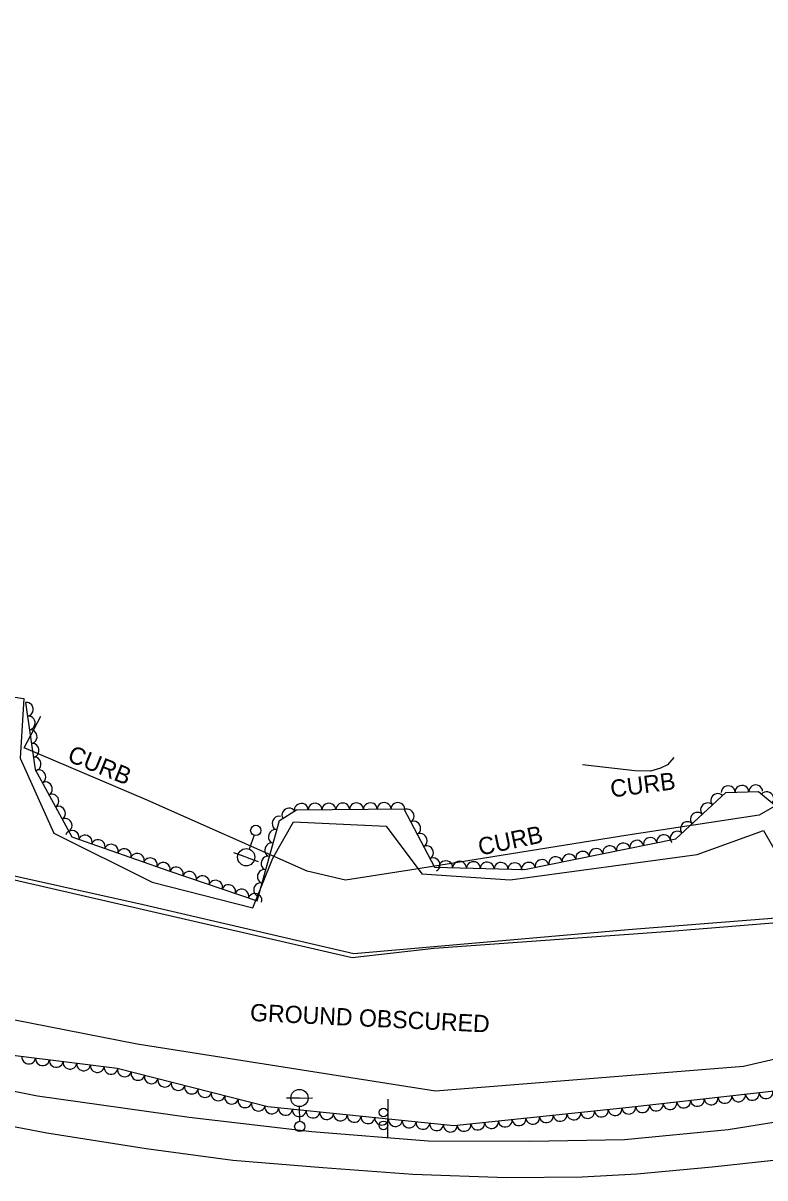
# Model space of a CAD drawing. Extents: x 1722896 to 1754269, y 648279 to 666297.
# Drawn here: x 1729327.9 to 1729542.8, y 652843.6 to 653178.1 of the extents above; entities that cross this region are included whole.
import ezdxf

# ---------------------------------------------------------------- set-up
doc = ezdxf.new("R2010")
doc.units = 0
for name, color, linetype in [('DESIGN - PUBLIC HEARING - Shapes', 7, 'Continuous'), ('DESIGN - SCRATCH - User 1', 7, 'Continuous'), ('SURVEY - CENTERLINE - Preliminary', 7, 'Continuous'), ('SURVEY - CENTERLINE - Preliminary Text', 7, 'Continuous'), ('SURVEY - DTM - Breaklines', 7, 'Continuous'), ('SURVEY - VEGETATION - Features with Text', 7, 'Continuous')]:
    doc.layers.add(name, color=color, linetype=linetype)

msp = doc.modelspace()

# ---------------------------------------------------------------- linework, layer by layer
at = {"layer": 'DESIGN - PUBLIC HEARING - Shapes'}
msp.add_line((1729433.54, 652866.38), (1729433.46, 652855.18), dxfattribs=at)
for centre in [(1729432.29, 652862.57), (1729432.26, 652858.82)]:
    msp.add_circle(centre, 1.25, dxfattribs=at)
at = {"layer": 'DESIGN - SCRATCH - User 1'}
for points in [[(1730402.95, 653127.46), (1730314.28, 653134.59), (1730219.17, 653162.83), (1730167.73, 653178.08), (1730100.62, 653177.14), (1730014.99, 653177.64), (1729990.41, 653163.02), (1729903.69, 653112.98), (1729836.86, 653073.47), (1729767.22, 653033.19), (1729728.41, 653010.36), (1729689.91, 652988.22), (1729640.73, 652959.93), (1729615.49, 652945.23), (1729574.28, 652921.03), (1729503.17, 652915.44), (1729423.74, 652908.46), (1729362.64, 652922.7), (1729266.32, 652944.1)], [(1729325.44, 652929.93), (1729423.21, 652907.47), (1729447.01, 652910.13), (1729515.48, 652915.11), (1729574.72, 652919.93), (1729618.03, 652944.86), (1729690.89, 652987.57), (1729742.07, 653016.84), (1729803.78, 653052.91), (1729873.89, 653094.15), (1729936.09, 653129.87), (1729994.48, 653163.92), (1730014.5, 653175.61), (1730021, 653175.83), (1730100.23, 653175.61), (1730167.67, 653176.58), (1730218.67, 653161.51), (1730268.57, 653146.66), (1730315.51, 653132.74), (1730411.72, 653125.99)]]:
    msp.add_lwpolyline(points, dxfattribs=at)
at = {"layer": 'SURVEY - CENTERLINE - Preliminary'}
for points in [[(1729307.77, 652985.42), (1729328.13, 652982.44), (1729327.01, 652965.19), (1729336.81, 652943.5), (1729365.32, 652929.31), (1729394.46, 652921.79), (1729400.28, 652936.17), (1729406.2, 652946.74), (1729433.08, 652945.51), (1729443.4, 652931.68), (1729469.04, 652929.95), (1729523.19, 652937.25), (1729542.35, 652944.25), (1729548.04, 652934.5)], [(1729579.47, 652885.83), (1729536.63, 652875.85), (1729447.41, 652868.7), (1729360.96, 652882.35), (1729268.83, 652900.44)]]:
    msp.add_lwpolyline(points, dxfattribs=at)
at = {"layer": 'SURVEY - CENTERLINE - Preliminary Text'}
for points in [[(1729963, 653167.59), (1729899.51, 653130.82), (1729894.39, 653138.3), (1729886.38, 653132.61), (1729890.7, 653126), (1729855.67, 653106.22), (1729807.21, 653078.99), (1729736.41, 653038.91), (1729700.34, 653018.37), (1729665.67, 652998.66), (1729621.6, 652973.6), (1729593.97, 652958.91), (1729586.08, 652970.67), (1729582.54, 652971.88), (1729578.25, 652969.91), (1729564.1, 652961.86), (1729541.14, 652948.7), (1729503.07, 652942.92), (1729440.49, 652932.87), (1729421.3, 652929.88), (1729410.15, 652932.46), (1729363.18, 652953.33), (1729328.22, 652968.2), (1729333.04, 652977.32)], [(1729516.4, 652965.39), (1729514.6, 652963.25), (1729512.59, 652962.27), (1729509.69, 652961.42), (1729505.15, 652961.52), (1729489.94, 652963.22)], [(1729332.06, 652867.31), (1729297.74, 652874.16), (1729251.92, 652884.16), (1729185.5, 652898.55), (1729112.25, 652914.71), (1729058.49, 652927.72), (1729008.62, 652939.2)], [(1729593.11, 652889.86), (1729590.97, 652879.49), (1729583.67, 652866.62), (1729562.77, 652862.48), (1729532.16, 652857.56), (1729502.1, 652854.67), (1729474.71, 652854.17), (1729445.23, 652854.27), (1729411.53, 652856.98), (1729375.99, 652861.08), (1729332.06, 652867.31)], [(1729545.25, 652848.67), (1729527.55, 652846.69), (1729505.69, 652844.72), (1729489.9, 652843.84), (1729467.9, 652843.61), (1729440.82, 652844.63), (1729414.69, 652846.51), (1729388.67, 652848.67), (1729363.54, 652851.99), (1729334.74, 652856.56), (1729293.83, 652864.36)]]:
    msp.add_lwpolyline(points, dxfattribs=at)
at = {"layer": 'SURVEY - DTM - Breaklines'}
for p, q in [((1729394.8, 652942.84), (1729393.36, 652938.84)), ((1729392.52, 652936.49), (1729388.99, 652937.75)), ((1729392.52, 652936.49), (1729396.04, 652935.22)), ((1729407.96, 652866.75), (1729404.21, 652866.71)), ((1729407.96, 652866.75), (1729411.71, 652866.8)), ((1729408.05, 652860), (1729407.99, 652864.25))]:
    msp.add_line(p, q, dxfattribs=at)
for centre, radius in [((1729395.3, 652944.25), 1.5), ((1729392.52, 652936.49), 2.5), ((1729407.96, 652866.75), 2.5), ((1729408.06, 652858.5), 1.5)]:
    msp.add_circle(centre, radius, dxfattribs=at)
at = {"layer": 'SURVEY - VEGETATION - Features with Text'}
for points in [[(1729975.99, 653117.37), (1729899.53, 653059.57), (1729865.08, 653028.08), (1729823.22, 653000), (1729781.82, 652967.28), (1729747.33, 652941.84), (1729709.92, 652918.75), (1729671.39, 652897.72), (1729627.16, 652881.54), (1729611.02, 652880.54), (1729603.59, 652887.52), (1729589.11, 652879.56), (1729560.05, 652870.34), (1729503.49, 652863.99), (1729452.68, 652858.67), (1729398.78, 652864.16), (1729355.14, 652875.31), (1729312.42, 652880.62)], [(1729328.62, 652981.34), (1729331.41, 652961.94), (1729341.98, 652942.35), (1729370.13, 652932.5), (1729395.7, 652923.86), (1729402.16, 652947.16), (1729407.14, 652950.17), (1729438.21, 652950.46), (1729447.12, 652933.64), (1729473.2, 652932.9), (1729517, 652941.81), (1729531.47, 652955.25), (1729540.99, 652955.56), (1729550.02, 652948.02)]]:
    msp.add_lwpolyline(points, dxfattribs=at)
for centre, major_axis in [((1729328.91, 652979.36), (0.28, -1.98)), ((1729329.48, 652975.4), (0.28, -1.98)), ((1729330.05, 652971.44), (0.28, -1.98)), ((1729330.62, 652967.48), (0.28, -1.98)), ((1729331.19, 652963.52), (0.28, -1.98)), ((1729332.55, 652959.83), (0.95, -1.76)), ((1729334.45, 652956.31), (0.95, -1.76)), ((1729532.15, 652955.27), (2, 0.06)), ((1729536.15, 652955.4), (2, 0.06)), ((1729540.15, 652955.53), (2, 0.06)), ((1729543.41, 652953.53), (1.54, -1.28)), ((1729336.35, 652952.79), (0.95, -1.76)), ((1729408.48, 652950.18), (2, 0.02)), ((1729412.48, 652950.22), (2, 0.02)), ((1729416.48, 652950.26), (2, 0.02)), ((1729420.48, 652950.3), (2, 0.02)), ((1729424.48, 652950.33), (2, 0.02)), ((1729428.48, 652950.37), (2, 0.02)), ((1729432.48, 652950.41), (2, 0.02)), ((1729436.47, 652950.45), (2, 0.02)), ((1729526.11, 652950.27), (1.47, 1.36)), ((1729529.04, 652952.99), (1.47, 1.36)), ((1729338.25, 652949.27), (0.95, -1.76)), ((1729404.86, 652948.79), (1.71, 1.03)), ((1729439.27, 652948.46), (0.94, -1.77)), ((1729523.18, 652947.55), (1.47, 1.36)), ((1729340.15, 652945.75), (0.95, -1.76)), ((1729401.94, 652946.34), (0.53, 1.93)), ((1729441.14, 652944.93), (0.94, -1.77)), ((1729520.25, 652944.83), (1.47, 1.36)), ((1729342.12, 652942.31), (1.89, -0.66)), ((1729345.89, 652940.99), (1.89, -0.66)), ((1729400.87, 652942.49), (0.53, 1.93)), ((1729443.01, 652941.39), (0.94, -1.77)), ((1729509.59, 652940.3), (1.96, 0.4)), ((1729513.5, 652941.1), (1.96, 0.4)), ((1729517.32, 652942.1), (1.47, 1.36)), ((1729349.67, 652939.66), (1.89, -0.66)), ((1729353.44, 652938.34), (1.89, -0.66)), ((1729357.22, 652937.02), (1.89, -0.66)), ((1729399.8, 652938.63), (0.53, 1.93)), ((1729444.88, 652937.86), (0.94, -1.77)), ((1729493.91, 652937.11), (1.96, 0.4)), ((1729497.83, 652937.91), (1.96, 0.4)), ((1729501.75, 652938.7), (1.96, 0.4)), ((1729505.67, 652939.5), (1.96, 0.4)), ((1729360.99, 652935.7), (1.89, -0.66)), ((1729364.77, 652934.38), (1.89, -0.66)), ((1729398.73, 652934.78), (0.53, 1.93)), ((1729446.75, 652934.32), (0.94, -1.77)), ((1729450.34, 652933.55), (2, -0.06)), ((1729454.34, 652933.43), (2, -0.06)), ((1729478.23, 652933.92), (1.96, 0.4)), ((1729482.15, 652934.72), (1.96, 0.4)), ((1729486.07, 652935.51), (1.96, 0.4)), ((1729489.99, 652936.31), (1.96, 0.4)), ((1729368.54, 652933.06), (1.89, -0.66)), ((1729372.33, 652931.76), (1.89, -0.64)), ((1729376.12, 652930.48), (1.89, -0.64)), ((1729397.66, 652930.93), (0.53, 1.93)), ((1729458.34, 652933.32), (2, -0.06)), ((1729462.34, 652933.2), (2, -0.06)), ((1729466.33, 652933.09), (2, -0.06)), ((1729470.33, 652932.98), (2, -0.06)), ((1729474.31, 652933.12), (1.96, 0.4)), ((1729379.91, 652929.2), (1.89, -0.64)), ((1729383.7, 652927.92), (1.89, -0.64)), ((1729387.49, 652926.64), (1.89, -0.64)), ((1729396.59, 652927.07), (0.53, 1.93)), ((1729391.28, 652925.36), (1.89, -0.64)), ((1729395.07, 652924.08), (1.89, -0.64)), ((1729329.54, 652878.49), (-1.98, 0.25)), ((1729333.51, 652878), (-1.98, 0.25)), ((1729337.48, 652877.51), (-1.98, 0.25)), ((1729341.45, 652877.01), (-1.98, 0.25)), ((1729345.42, 652876.52), (-1.98, 0.25)), ((1729349.39, 652876.03), (-1.98, 0.25)), ((1729353.36, 652875.53), (-1.98, 0.25)), ((1729357.27, 652874.77), (-1.94, 0.49)), ((1729361.15, 652873.78), (-1.94, 0.49)), ((1729365.02, 652872.79), (-1.94, 0.49)), ((1729368.9, 652871.8), (-1.94, 0.49)), ((1729372.78, 652870.81), (-1.94, 0.49)), ((1729376.65, 652869.82), (-1.94, 0.49)), ((1729380.53, 652868.83), (-1.94, 0.49)), ((1729543.13, 652868.44), (-1.99, -0.22)), ((1729384.4, 652867.84), (-1.94, 0.49)), ((1729388.28, 652866.85), (-1.94, 0.49)), ((1729392.15, 652865.86), (-1.94, 0.49)), ((1729396.03, 652864.87), (-1.94, 0.49)), ((1729515.31, 652865.31), (-1.99, -0.22)), ((1729519.28, 652865.76), (-1.99, -0.22)), ((1729523.26, 652866.21), (-1.99, -0.22)), ((1729527.23, 652866.65), (-1.99, -0.22)), ((1729531.21, 652867.1), (-1.99, -0.22)), ((1729535.18, 652867.55), (-1.99, -0.22)), ((1729539.16, 652867.99), (-1.99, -0.22)), ((1729399.93, 652864.05), (-1.99, 0.2)), ((1729403.91, 652863.64), (-1.99, 0.2)), ((1729407.89, 652863.24), (-1.99, 0.2)), ((1729411.87, 652862.83), (-1.99, 0.2)), ((1729415.85, 652862.42), (-1.99, 0.2)), ((1729419.83, 652862.02), (-1.99, 0.2)), ((1729423.81, 652861.61), (-1.99, 0.2)), ((1729483.49, 652861.89), (-1.99, -0.21)), ((1729487.47, 652862.31), (-1.99, -0.21)), ((1729491.45, 652862.73), (-1.99, -0.21)), ((1729495.43, 652863.14), (-1.99, -0.21)), ((1729499.41, 652863.56), (-1.99, -0.21)), ((1729503.38, 652863.98), (-1.99, -0.21)), ((1729507.36, 652864.42), (-1.99, -0.22)), ((1729511.33, 652864.87), (-1.99, -0.22)), ((1729427.79, 652861.21), (-1.99, 0.2)), ((1729431.77, 652860.8), (-1.99, 0.2)), ((1729435.75, 652860.39), (-1.99, 0.2)), ((1729439.73, 652859.99), (-1.99, 0.2)), ((1729443.71, 652859.58), (-1.99, 0.2)), ((1729447.69, 652859.18), (-1.99, 0.2)), ((1729451.67, 652858.77), (-1.99, 0.2)), ((1729455.65, 652858.98), (-1.99, -0.21)), ((1729459.62, 652859.39), (-1.99, -0.21)), ((1729463.6, 652859.81), (-1.99, -0.21)), ((1729467.58, 652860.23), (-1.99, -0.21)), ((1729471.56, 652860.64), (-1.99, -0.21)), ((1729475.54, 652861.06), (-1.99, -0.21)), ((1729479.51, 652861.48), (-1.99, -0.21))]:
    msp.add_ellipse(centre, major_axis=major_axis, ratio=0.940188, start_param=0, end_param=3.141593, dxfattribs=at)

# ---------------------------------------------------------------- texts
at = {"layer": 'DESIGN - SCRATCH - User 1'}
for rotation, p in [(337.8537, (1729340.41, 652964.42)), (7.466, (1729498.35, 652953.76)), (11.9244, (1729460.29, 652936.93))]:
    msp.add_text('CURB', height=5, rotation=rotation, dxfattribs=at).set_placement(p)
at = {"layer": 'SURVEY - CENTERLINE - Preliminary'}
msp.add_text('GROUND OBSCURED', height=5, rotation=357.219, dxfattribs=at).set_placement((1729393.55, 652889.08))

doc.saveas('drawing.dxf')
